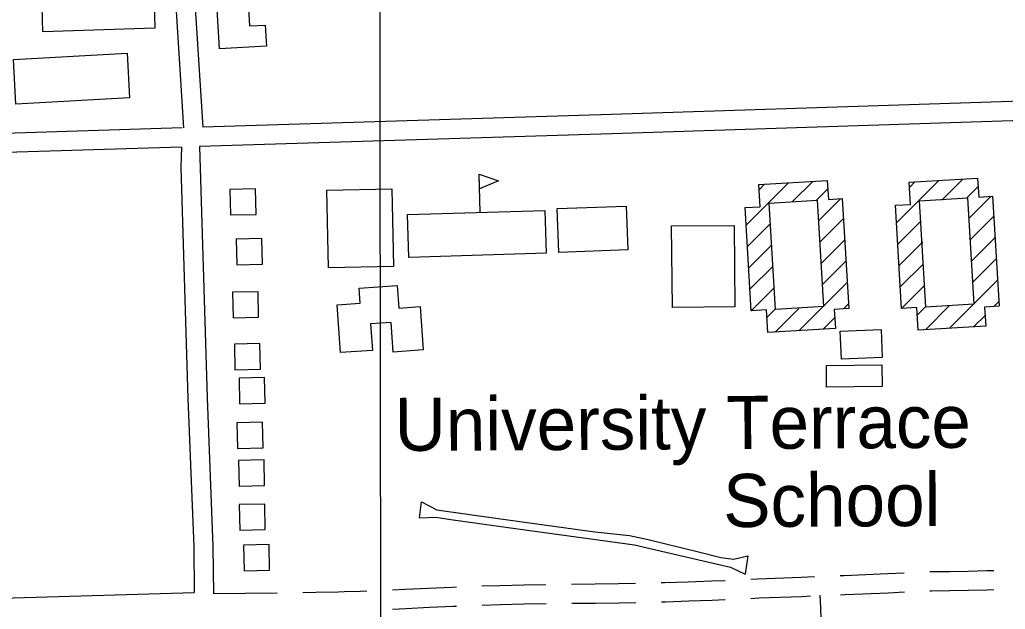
# Model space of a CAD drawing. Extents: x 3297716 to 3335574, y 688621 to 713991.
# Drawn here: x 3327549 to 3329089, y 698134 to 699056 of the extents above; entities that cross this region are included whole.
import ezdxf

# ---------------------------------------------------------------- set-up
doc = ezdxf.new("R2010")
doc.units = 0
for name, color, linetype in [('V-BLDG-IDEN', 7, 'Continuous'), ('V-BLDG-OTLN', 7, 'Continuous'), ('V-GRID-MAJR', 7, 'Continuous'), ('V-ROAD-CNTR', 7, 'Continuous'), ('V-TOPO-SHOR', 7, 'Continuous')]:
    doc.layers.add(name, color=color, linetype=linetype)

msp = doc.modelspace()

# ---------------------------------------------------------------- linework, layer by layer
at = {"layer": 'V-BLDG-OTLN'}
for p, q in [((3328268.760425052, 698754.457464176), (3328266.9704286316, 698814.4303442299)), ((3328684.2025941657, 698734.4725041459), (3328750.4874615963, 698800.756371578)), ((3328704.2695540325, 698789.894393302), (3328712.94053669, 698798.5653759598)), ((3328755.9814506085, 698770.8944313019), (3328788.0333865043, 698802.9473671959)), ((3328919.0301245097, 698738.111496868), (3328985.3149919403, 698804.3953643)), ((3328939.0970843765, 698793.5333860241), (3328947.768067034, 698802.2043686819)), ((3328989.977982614, 698773.703425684), (3329022.8609168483, 698806.5863599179)), ((3328793.5343755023, 698773.0924269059), (3328811.6683392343, 698791.2263906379)), ((3329028.743905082, 698777.1124188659), (3329046.4958695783, 698794.86538336)), ((3328798.113366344, 698742.316488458), (3328831.6042993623, 698775.808421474)), ((3329032.110898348, 698745.1254828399), (3329066.4318297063, 698779.447414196)), ((3328686.1525902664, 698701.0665709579), (3328722.037518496, 698736.9504991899)), ((3328799.7833630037, 698708.6315558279), (3328836.1762902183, 698745.0244830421)), ((3328920.9801206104, 698704.7055636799), (3328957.7310471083, 698741.4564901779)), ((3329033.538895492, 698711.1975506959), (3329071.0038205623, 698748.6634757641)), ((3328800.7263611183, 698674.2186246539), (3328838.1252863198, 698711.617549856)), ((3328922.93011671, 698671.299630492), (3328960.129042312, 698708.4985560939)), ((3329035.935890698, 698678.2386166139), (3329072.952816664, 698715.256542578)), ((3328688.1025863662, 698667.66063777), (3328724.4345137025, 698703.9925651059)), ((3328802.88035681, 698641.0186910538), (3328840.073282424, 698678.2106166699)), ((3328924.879112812, 698637.8946973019), (3328961.0710404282, 698674.0856249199)), ((3329038.3318859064, 698645.2816825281), (3329074.900812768, 698681.849609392)), ((3328690.051582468, 698634.2557045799), (3328726.346509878, 698670.5496319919)), ((3328766.90042877, 698569.6828337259), (3328842.0222785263, 698644.8046834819)), ((3329001.727959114, 698573.321826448), (3329076.8498088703, 698648.443676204)), ((3328692.001578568, 698600.8497713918), (3328728.258506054, 698637.1066988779)), ((3328926.829108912, 698604.4887641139), (3328963.226036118, 698640.8856913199)), ((3329071.072820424, 698607.3117584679), (3329078.797804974, 698615.036743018)), ((3328716.4905295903, 698589.9827931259), (3328730.656501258, 698604.1487647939)), ((3328729.3545038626, 698567.4928381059), (3328766.269430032, 698604.407764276)), ((3328836.24529008, 698603.6727657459), (3328843.97027463, 698611.3977502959)), ((3328951.3180599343, 698593.6217858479), (3328965.381031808, 698607.6837577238)), ((3328964.1820342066, 698571.1318308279), (3329001.2359600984, 698608.1857567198)), ((3328804.4453536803, 698571.872829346), (3328822.502317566, 698589.929793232)), ((3329039.2728840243, 698575.511822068), (3329057.32984791, 698593.568785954))]:
    msp.add_line(p, q, dxfattribs=at)
for points in [[(3327584.1837942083, 699076.43982021), (3327759.04244449, 699081.935809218), (3327760.2894419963, 699042.245888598), (3327585.4307917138, 699036.7528995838)], [(3327934.808092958, 699014.407944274), (3327861.193240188, 699010.220952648), (3327857.2162481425, 699080.1448128), (3327905.936150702, 699082.9158072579), (3327908.0491464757, 699045.7628815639), (3327932.945096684, 699047.178878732)], [(3327720.97252063, 698933.2921065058), (3327543.155876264, 698923.4681261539), (3327539.296883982, 698993.3159864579), (3327717.113528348, 699003.1409668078)], [(3328266.9704286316, 698814.4303442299), (3328297.30136797, 698803.78036553), (3328267.659427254, 698791.3393904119)], [(3328692.001578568, 698600.8497713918), (3328682.5965973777, 698761.994449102), (3328705.818550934, 698763.3494463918), (3328703.7945549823, 698798.031377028), (3328810.9063407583, 698804.2823645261), (3328812.632337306, 698774.701423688), (3328834.371293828, 698775.9694211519), (3328844.3932737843, 698604.147764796), (3328821.7503190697, 698602.826767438), (3328823.491315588, 698572.9838271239), (3328717.841526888, 698566.8208394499), (3328715.77553102, 698602.2367686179)], [(3328926.829108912, 698604.4887641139), (3328917.4241277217, 698765.633441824), (3328940.646081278, 698766.9884391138), (3328938.6220853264, 698801.67036975), (3329045.7338711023, 698807.9213572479), (3329047.45986765, 698778.34041641), (3329069.198824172, 698779.6084138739), (3329079.2208041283, 698607.7867575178), (3329056.5778494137, 698606.46576016), (3329058.318845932, 698576.6228198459), (3328952.669057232, 698570.4598321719), (3328950.603061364, 698605.8757613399)], [(3327877.6882071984, 698790.3563923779), (3327878.628205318, 698750.3684723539), (3327918.6171253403, 698751.308470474), (3327917.676127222, 698791.297390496)], [(3328029.025904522, 698789.078394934), (3328130.6567012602, 698791.1393908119), (3328133.1136963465, 698670.00563308), (3328031.4818996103, 698667.9446372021)], [(3328730.0165025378, 698602.9437672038), (3328720.2885219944, 698769.0084350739), (3328795.288371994, 698773.401426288), (3328805.01535254, 698607.3367584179)], [(3328964.844032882, 698606.5827599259), (3328955.1160523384, 698772.6474277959), (3329030.115902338, 698777.04041901), (3329039.842882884, 698610.9757511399)], [(3328155.09665238, 698751.0644709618), (3328369.7012231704, 698757.4704581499), (3328371.6992191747, 698690.5365920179), (3328157.094648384, 698684.13060483)], [(3328388.7861850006, 698760.3054524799), (3328496.52096953, 698764.419444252), (3328499.138964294, 698695.8725813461), (3328391.404179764, 698691.7585895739)], [(3328665.50063157, 698734.1745047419), (3328666.5966293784, 698606.781759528), (3328568.794824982, 698605.9407612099), (3328567.698827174, 698733.333506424)], [(3327887.41218775, 698712.577547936), (3327888.35218587, 698672.5896279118), (3327928.3411058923, 698673.5296260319), (3327927.400107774, 698713.5185460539)], [(3327881.513199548, 698629.5957138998), (3327882.4531976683, 698589.607793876), (3327922.44211769, 698590.547791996), (3327921.501119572, 698630.5367120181)], [(3328050.485861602, 698535.35090239), (3328045.205872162, 698609.9657531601), (3328080.9588006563, 698612.4957480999), (3328079.30680396, 698635.8417014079), (3328138.919684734, 698640.059692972), (3328141.41167975, 698604.8367634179), (3328174.580613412, 698607.183758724), (3328179.365603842, 698539.562893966), (3328132.838696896, 698536.27090055), (3328129.558703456, 698582.6328078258), (3328097.348767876, 698580.353812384), (3328100.283762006, 698538.8748953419)], [(3328831.199300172, 698568.6238358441), (3328894.792172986, 698571.5288300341), (3328896.7881689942, 698527.838917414), (3328833.19529618, 698524.933923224)], [(3327884.5651934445, 698548.373876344), (3327885.505191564, 698508.3859563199), (3327925.4941115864, 698509.3259544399), (3327924.5531134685, 698549.3148744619)], [(3328809.41534374, 698515.0229430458), (3328896.083170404, 698516.004941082), (3328896.464169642, 698482.3700083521), (3328809.7963429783, 698481.389010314)], [(3327891.8381788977, 698495.26098257), (3327892.7781770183, 698455.273062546), (3327932.76709704, 698456.2130606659), (3327931.8260989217, 698496.2019806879)], [(3327888.5061855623, 698425.515122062), (3327889.446183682, 698385.5272020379), (3327929.435103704, 698386.4672001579), (3327928.4941055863, 698426.4561201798)], [(3327890.884180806, 698366.7282396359), (3327891.824178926, 698326.7403196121), (3327931.813098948, 698327.6803177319), (3327930.87210083, 698367.6692377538)], [(3327891.9251787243, 698297.8043774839), (3327892.8651768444, 698257.8164574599), (3327932.854096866, 698258.75645558), (3327931.9130987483, 698298.745375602)], [(3327898.7021651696, 698234.487504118), (3327899.64216329, 698194.4995840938), (3327939.631083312, 698195.4395822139), (3327938.690085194, 698235.4285022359)]]:
    msp.add_lwpolyline(points, close=True, dxfattribs=at)
at = {"layer": 'V-GRID-MAJR'}
msp.add_spline([(3328118.71, 694026.179), (3328114.745, 697055.047), (3328106.81, 703116.6240000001), (3328098.875, 709178.229), (3328094.9050000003, 712210.951)], degree=3, dxfattribs=at)
at = {"layer": 'V-ROAD-CNTR'}
msp.add_line((3327851.628403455, 698158.8798391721), (3327951.617285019, 698159.9079362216), dxfattribs=at)
for points in [[(3327782.009398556, 699595.3187824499), (3327788.6063853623, 699309.32435444), (3327791.2483800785, 699110.8487513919), (3327805.131352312, 698886.593199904)], [(3327822.0223185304, 699099.27977453), (3327835.1312923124, 698887.5201980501)], [(3329724.0385144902, 698948.252076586), (3328473.514015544, 698907.226158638), (3327835.1312923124, 698887.5201980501)], [(3329115.608731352, 698898.2751765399), (3328474.4680136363, 698877.242218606), (3327830.0433024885, 698857.348258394)], [(3327802.84735688, 698886.5222000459), (3327508.8059449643, 698877.4462181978), (3327368.707225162, 698874.3072244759)], [(3327801.946358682, 698856.4802601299), (3327509.603943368, 698847.456278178), (3327371.0192205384, 698844.3522843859)], [(3327801.946358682, 698856.4802601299), (3327801.0073605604, 698825.1503227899), (3327811.9973385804, 698463.368046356), (3327821.0503204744, 698231.587509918), (3327821.938318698, 698160.35665238)], [(3327830.0433024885, 698857.348258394), (3327841.979278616, 698464.4080442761), (3327851.0422604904, 698232.359508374), (3327851.9630995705, 698158.5631818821)], [(3328691.23437844, 698181.3341824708), (3328702.5010438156, 698181.8861480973), (3328770.0559437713, 698184.4365227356), (3328791.1538528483, 698185.2927103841)], [(3328831.120536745, 698186.9157841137), (3328837.496705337, 698187.1747672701), (3328904.930631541, 698190.1078937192), (3328931.023180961, 698191.3179840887)], [(3328970.980219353, 698193.1710658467), (3328972.6558501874, 698193.2487763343), (3329001.9930409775, 698193.520855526), (3329030.9931021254, 698193.998079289), (3329059.991427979, 698194.6845304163), (3329070.959698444, 698195.0226245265)], [(3328131.5366361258, 698164.636400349), (3328151.0510085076, 698165.4991304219), (3328188.094847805, 698167.3870203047), (3328225.2490984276, 698169.0403478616), (3328231.42751445, 698169.2748699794)], [(3328271.400741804, 698170.7329701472), (3328299.587024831, 698171.617141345), (3328336.7672808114, 698172.5435646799), (3328371.369234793, 698173.179866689)], [(3328411.3660102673, 698173.6677416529), (3328448.2159097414, 698173.8654321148), (3328484.5214265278, 698174.3778867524), (3328511.3559959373, 698174.9136790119)], [(3328551.3439939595, 698175.8872256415), (3328557.1668308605, 698176.0369228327), (3328593.480929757, 698177.1821821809), (3328629.7892274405, 698178.5369470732), (3328651.2786135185, 698179.4636159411)], [(3327394.20817416, 698151.1116708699), (3327415.0271325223, 698148.4376762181), (3327821.938318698, 698160.35665238)], [(3327991.611545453, 698160.4178778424), (3328011.8820418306, 698160.7639453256), (3328046.687040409, 698161.5945350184), (3328056.2921088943, 698161.8879790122), (3328081.48281597, 698162.660406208), (3328091.57044083, 698163.037694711)], [(3328691.5436920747, 698151.3133558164), (3328703.8009561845, 698151.9138519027), (3328771.2300562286, 698154.4594772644), (3328784.565325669, 698155.0006443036)], [(3328805.5215124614, 697991.2878809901), (3328804.988, 698019.886), (3328804.146, 698047.407), (3328803.063, 698074.92), (3328801.736, 698102.421), (3328800.568, 698136.518), (3328799.811143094, 698156.1243896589)], [(3328831.4294625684, 698156.9035955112), (3328838.757294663, 698157.20123273), (3328906.277368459, 698160.1381062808), (3328931.3323476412, 698161.3000774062)], [(3328971.289385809, 698163.1531591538), (3328973.490149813, 698163.2552236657), (3329002.3789590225, 698163.523144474), (3329031.594897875, 698164.0039207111), (3329060.808572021, 698164.6954695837), (3329071.268477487, 698165.0178934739)], [(3328131.845732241, 698134.6207619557), (3328152.4769914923, 698135.5328695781), (3328189.5251521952, 698137.4209796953), (3328226.4849015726, 698139.0656521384), (3328231.7363409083, 698139.2649878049)], [(3328271.709401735, 698140.7278960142), (3328300.430975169, 698141.628858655), (3328337.416719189, 698142.5504353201), (3328371.6777476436, 698143.1804679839)], [(3328411.6745096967, 698143.6689649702), (3328448.5080902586, 698143.8665678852), (3328485.0325734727, 698144.3821132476), (3328511.6645171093, 698144.913859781)], [(3328551.652564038, 698145.8852461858), (3328558.0251691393, 698146.0490771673), (3328594.513070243, 698147.1998178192), (3328630.9947725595, 698148.5610529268), (3328651.587633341, 698149.4490616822)]]:
    msp.add_lwpolyline(points, dxfattribs=at)
at = {"layer": 'V-TOPO-SHOR'}
for points in [[(3328173.549, 698277.252), (3328176.9560000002, 698302.275), (3328201.092, 698289.479), (3328292.968, 698276.7220000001), (3328447.792, 698255.439), (3328501.761, 698249.365), (3328531.06, 698243.169), (3328609.551, 698223.902), (3328644.699, 698215.292), (3328664.634, 698212.331), (3328686.62, 698217.571), (3328682.3910000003, 698189.033)], [(3328173.549, 698277.252), (3328199.401, 698278.143), (3328222.8540000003, 698274.36), (3328327.632, 698259.895), (3328456.6520000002, 698242.029), (3328509.828, 698235.18), (3328558.642, 698223.287), (3328659.4080000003, 698199.86), (3328682.3910000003, 698189.033)]]:
    msp.add_lwpolyline(points, dxfattribs=at)

# ---------------------------------------------------------------- texts
at = {"layer": 'V-BLDG-IDEN'}
for s, p in [('University Terrace', (3328135.023650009, 698381.5894848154)), ('School', (3328648.3830857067, 698262.567449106))]:
    msp.add_text(s, height=82.99983200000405, rotation=0.3244054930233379, dxfattribs=at).set_placement(p)

doc.saveas('drawing.dxf')
